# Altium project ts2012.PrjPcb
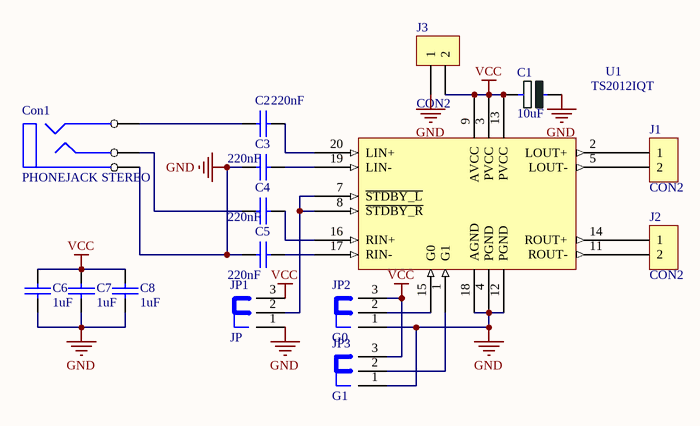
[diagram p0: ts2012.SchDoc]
1 sheet, 16 parts. Net scope: global (net labels, ports and power ports of the same name join across sheets).
Board file: ts2012.PcbDoc

## Sheet ts2012.SchDoc
size A4

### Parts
C1  10uF  [CE_SMD_W]
C2  220nF  [0805]
C3  220nF  [0805]
C4  220nF  [0805]
C5  220nF  [0805]
C6  1uF  [0805]
C7  1uF  [0805]
C8  1uF  [0805]
Con1  PHONEJACK STEREO  [MINIJACK_STEREO]
J1  CON2  [ARK2]
J2  CON2  [ARK2]
J3  CON2  [ARK2]
JP1  JP  [sip-3]
JP2  G0  [sip-3]
JP3  G1  [sip-3]
U1  TS2012IQT  [QFN20_4X4]

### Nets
GND: C1.2(MINUS) C3.1 C5.1 C6.2 C7.2 C8.2 Con1.5 J3.1 JP1.1 JP2.1 JP3.1 U1.4(PGND) U1.12(PGND) U1.18(AGND)
VCC: C1.1(PLUS) C6.1 C7.1 C8.1 J3.2 JP1.3 JP2.3 JP3.3 U1.3(PVCC) U1.9(AVCC) U1.13(PVCC)
NetC2_1: C2.1 Con1.4
NetC2_2: C2.2 U1.20(LIN+)
NetC3_2: C3.2 U1.19(LIN-)
NetC4_1: C4.1 Con1.1
NetC4_2: C4.2 U1.16(RIN+)
NetC5_2: C5.2 U1.17(RIN-)
NetJ1_1: J1.1 U1.2(LOUT+)
NetJ1_2: J1.2 U1.5(LOUT-)
NetJ2_1: J2.1 U1.14(ROUT+)
NetJ2_2: J2.2 U1.11(ROUT-)
NetJP1_2: JP1.2 U1.7(~{STDBY_L}) U1.8(~{STDBY_R})
NetJP2_2: JP2.2 U1.15(G0)
NetJP3_2: JP3.2 U1.1(G1)

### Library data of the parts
C1 = CP: Capacitor
C2-C8 = Cap: Capacitor
J1-J3 = CON2: Connector
JP1-JP3 = JP: Jumper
